(* Logix 5000 project; controller AMCI_3204_AOP_AOI_sample_RSLogix_V28 vendor 1 type 14 code 92 rev 28.11; software revision 28.00; part 2 of 3 *)

ADD_ON_INSTRUCTION AMCI_3204_AOP_Manual_Move_CW   (* revision 1.0, vendor AMCI, ExecuteEnableInFalse *)
VAR_INPUT
   axis_status_bits : INT; {required}
   channel_number : INT; {required}
   _0_normal_1_S_Curve_Acceleration : BOOL;
   _0_Triangular_1_Trapezoidal_S_Curve : BOOL;
   Programmed_speed : DINT; {required}
   Acceleration : DINT; {required}
   Deceleration : DINT; {required}
END_VAR
VAR_IN_OUT
   AMCI_3204_output_data : AM:1756_3204:O:0; {required}
END_VAR
VAR_OUTPUT
   EN : BOOL; {access Read Only, visible}
   Manual_Move_CW_occurring : BOOL; {access Read Only, visible}
   ER : BOOL; {access Read Only, visible}
END_VAR
VAR
   command_data_block : DINT[8]; {access None}
END_VAR

ROUTINE EnableInFalse   (* ladder *)
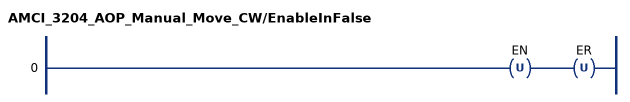
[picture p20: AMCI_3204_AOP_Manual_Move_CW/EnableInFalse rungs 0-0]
   0: OTU(EN)OTU(ER);
END_ROUTINE

ROUTINE Logic   (* ladder *)
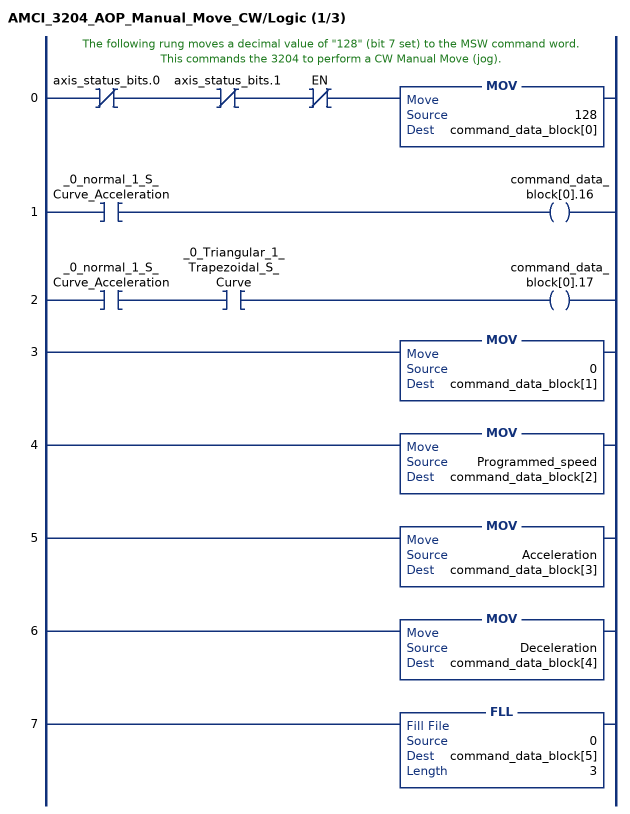
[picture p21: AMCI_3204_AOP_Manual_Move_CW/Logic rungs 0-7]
   // The following rung moves a decimal value of "128" (bit 7 set) to the MSW command word.  This commands the 3204 to perform a CW Manual Move (jog).
   0: XIO(axis_status_bits.0)XIO(axis_status_bits.1)XIO(EN)MOV(128,command_data_block[0]);
   1: XIC(_0_normal_1_S_Curve_Acceleration)OTE(command_data_block[0].16);
   2: XIC(_0_normal_1_S_Curve_Acceleration)XIC(_0_Triangular_1_Trapezoidal_S_Curve)OTE(command_data_block[0].17);
   3: MOV(0,command_data_block[1]);
   4: MOV(Programmed_speed,command_data_block[2]);
   5: MOV(Acceleration,command_data_block[3]);
   6: MOV(Deceleration,command_data_block[4]);
   7: FLL(0,command_data_block[5],3);
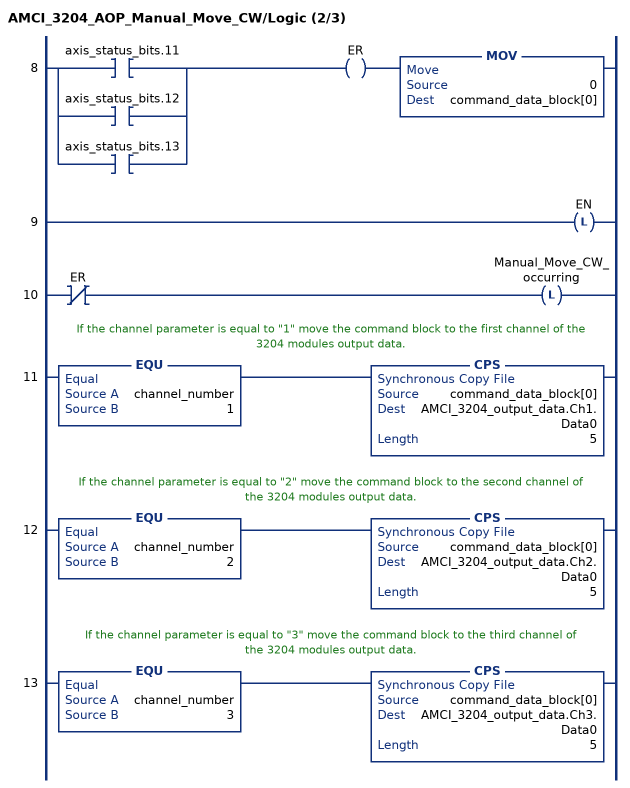
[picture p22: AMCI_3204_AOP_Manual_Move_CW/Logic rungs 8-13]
   8: [XIC(axis_status_bits.11) ,XIC(axis_status_bits.12) ,XIC(axis_status_bits.13) ]OTE(ER)MOV(0,command_data_block[0]);
   9: OTL(EN);
   10: XIO(ER)OTL(Manual_Move_CW_occurring);
   // If the channel parameter is equal to "1" move the command block to the first channel of the 3204 modules output data.
   11: EQU(channel_number,1)CPS(command_data_block[0],AMCI_3204_output_data.Ch1.Data0,5);
   // If the channel parameter is equal to "2" move the command block to the second channel of the 3204 modules output data.
   12: EQU(channel_number,2)CPS(command_data_block[0],AMCI_3204_output_data.Ch2.Data0,5);
   // If the channel parameter is equal to "3" move the command block to the third channel of the 3204 modules output data.
   13: EQU(channel_number,3)CPS(command_data_block[0],AMCI_3204_output_data.Ch3.Data0,5);
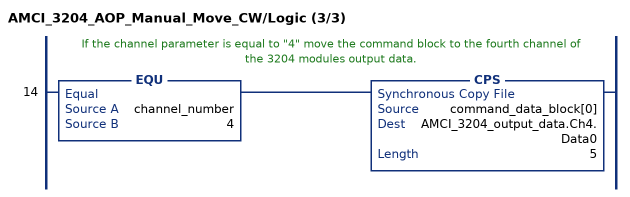
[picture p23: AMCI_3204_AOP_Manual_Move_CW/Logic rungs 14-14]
   // If the channel parameter is equal to "4" move the command block to the fourth channel of the 3204 modules output data.
   14: EQU(channel_number,4)CPS(command_data_block[0],AMCI_3204_output_data.Ch4.Data0,5);
END_ROUTINE
END_ADD_ON_INSTRUCTION

ADD_ON_INSTRUCTION AMCI_3204_AOP_Preset   (* revision 1.0, vendor AMCI, ExecuteEnableInFalse *)
VAR_INPUT
   axis_status_bits : INT; {required}
   channel_number : INT; {required}
   Target_Position : DINT; {required}
END_VAR
VAR_IN_OUT
   AMCI_3204_output_data : AM:1756_3204:O:0; {required}
END_VAR
VAR_OUTPUT
   EN : BOOL; {access Read Only, visible}
   ER : BOOL; {access Read Only, visible}
END_VAR
VAR
   command_data_block : DINT[8]; {access None}
END_VAR

ROUTINE EnableInFalse   (* ladder *)
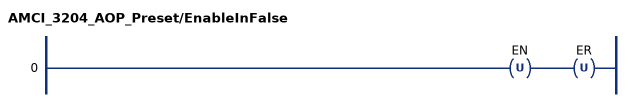
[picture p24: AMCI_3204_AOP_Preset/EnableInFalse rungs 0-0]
   0: OTU(EN)OTU(ER);
END_ROUTINE

ROUTINE Logic   (* ladder *)
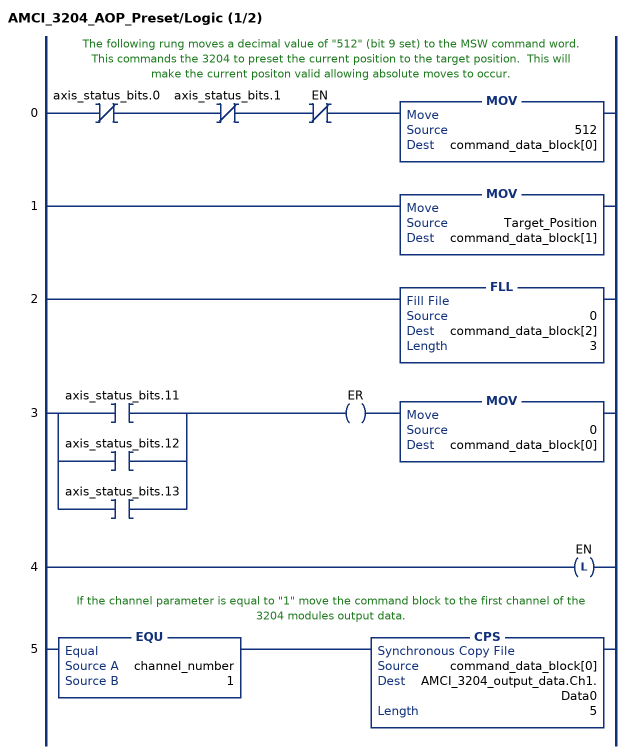
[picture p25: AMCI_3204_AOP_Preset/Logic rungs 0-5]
   // The following rung moves a decimal value of "512" (bit 9 set) to the MSW command word.  This commands the 3204 to preset the current position to the target position.  This will make the current positon valid allowing absolute moves to occur.
   0: XIO(axis_status_bits.0)XIO(axis_status_bits.1)XIO(EN)MOV(512,command_data_block[0]);
   1: MOV(Target_Position,command_data_block[1]);
   2: FLL(0,command_data_block[2],3);
   3: [XIC(axis_status_bits.11) ,XIC(axis_status_bits.12) ,XIC(axis_status_bits.13) ]OTE(ER)MOV(0,command_data_block[0]);
   4: OTL(EN);
   // If the channel parameter is equal to "1" move the command block to the first channel of the 3204 modules output data.
   5: EQU(channel_number,1)CPS(command_data_block[0],AMCI_3204_output_data.Ch1.Data0,5);
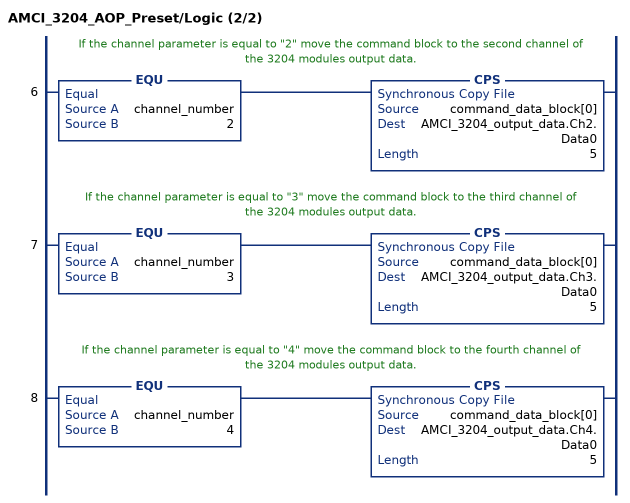
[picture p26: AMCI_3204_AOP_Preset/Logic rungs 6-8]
   // If the channel parameter is equal to "2" move the command block to the second channel of the 3204 modules output data.
   6: EQU(channel_number,2)CPS(command_data_block[0],AMCI_3204_output_data.Ch2.Data0,5);
   // If the channel parameter is equal to "3" move the command block to the third channel of the 3204 modules output data.
   7: EQU(channel_number,3)CPS(command_data_block[0],AMCI_3204_output_data.Ch3.Data0,5);
   // If the channel parameter is equal to "4" move the command block to the fourth channel of the 3204 modules output data.
   8: EQU(channel_number,4)CPS(command_data_block[0],AMCI_3204_output_data.Ch4.Data0,5);
END_ROUTINE
END_ADD_ON_INSTRUCTION

ADD_ON_INSTRUCTION AMCI_3204_AOP_Relative_Move   (* revision 1.0, vendor AMCI, ExecuteEnableInFalse *)
VAR_INPUT
   axis_status_bits : INT; {required}
   channel_number : INT; {required}
   _0_normal_1_S_Curve_Acceleration : BOOL;
   _0_Triangular_1_Trapezoidal_S_Curve : BOOL;
   Target_Position : DINT; {required}
   Programmed_speed : DINT; {required}
   Acceleration : DINT; {required}
   Deceleration : DINT; {required}
END_VAR
VAR_IN_OUT
   AMCI_3204_output_data : AM:1756_3204:O:0; {required}
END_VAR
VAR_OUTPUT
   EN : BOOL; {access Read Only, visible}
   ER : BOOL; {access Read Only, visible}
END_VAR
VAR
   command_data_block : DINT[8]; {access None}
END_VAR

ROUTINE EnableInFalse   (* ladder *)
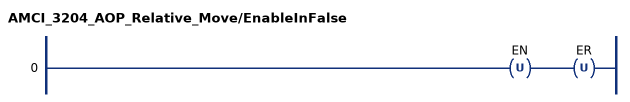
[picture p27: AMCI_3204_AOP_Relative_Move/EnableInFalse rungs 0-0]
   0: OTU(EN)OTU(ER);
END_ROUTINE

ROUTINE Logic   (* ladder *)
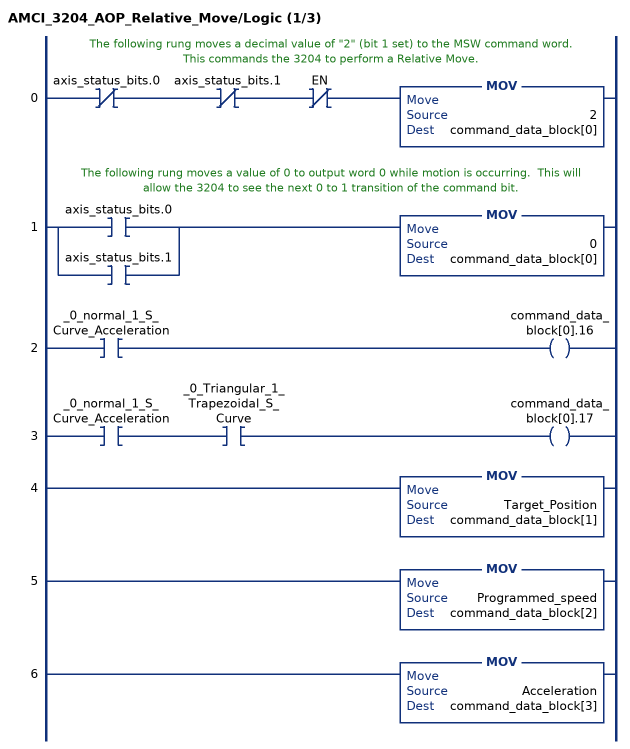
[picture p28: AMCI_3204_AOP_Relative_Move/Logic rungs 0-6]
   // The following rung moves a decimal value of "2" (bit 1 set) to the MSW command word.  This commands the 3204 to perform a Relative Move.
   0: XIO(axis_status_bits.0)XIO(axis_status_bits.1)XIO(EN)MOV(2,command_data_block[0]);
   // The following rung moves a value of 0 to output word 0 while motion is occurring.  This will allow the 3204 to see the next 0 to 1 transition of the command bit.
   1: [XIC(axis_status_bits.0) ,XIC(axis_status_bits.1) ]MOV(0,command_data_block[0]);
   2: XIC(_0_normal_1_S_Curve_Acceleration)OTE(command_data_block[0].16);
   3: XIC(_0_normal_1_S_Curve_Acceleration)XIC(_0_Triangular_1_Trapezoidal_S_Curve)OTE(command_data_block[0].17);
   4: MOV(Target_Position,command_data_block[1]);
   5: MOV(Programmed_speed,command_data_block[2]);
   6: MOV(Acceleration,command_data_block[3]);
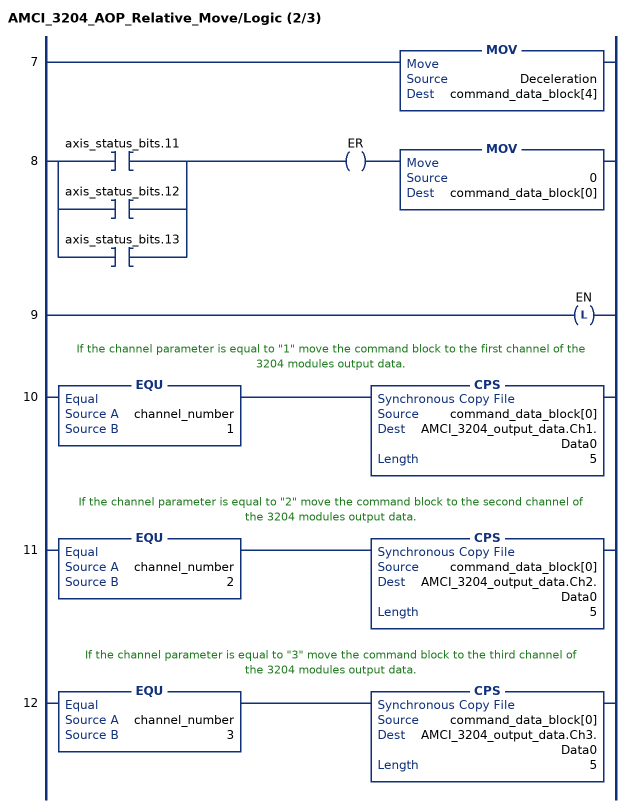
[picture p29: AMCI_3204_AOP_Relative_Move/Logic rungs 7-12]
   7: MOV(Deceleration,command_data_block[4]);
   8: [XIC(axis_status_bits.11) ,XIC(axis_status_bits.12) ,XIC(axis_status_bits.13) ]OTE(ER)MOV(0,command_data_block[0]);
   9: OTL(EN);
   // If the channel parameter is equal to "1" move the command block to the first channel of the 3204 modules output data.
   10: EQU(channel_number,1)CPS(command_data_block[0],AMCI_3204_output_data.Ch1.Data0,5);
   // If the channel parameter is equal to "2" move the command block to the second channel of the 3204 modules output data.
   11: EQU(channel_number,2)CPS(command_data_block[0],AMCI_3204_output_data.Ch2.Data0,5);
   // If the channel parameter is equal to "3" move the command block to the third channel of the 3204 modules output data.
   12: EQU(channel_number,3)CPS(command_data_block[0],AMCI_3204_output_data.Ch3.Data0,5);
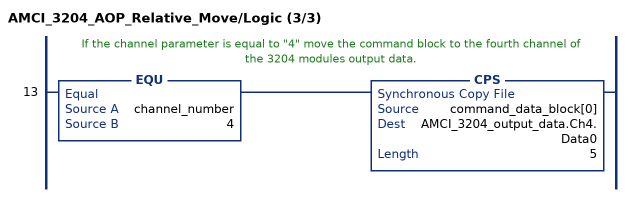
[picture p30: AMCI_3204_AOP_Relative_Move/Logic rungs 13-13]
   // If the channel parameter is equal to "4" move the command block to the fourth channel of the 3204 modules output data.
   13: EQU(channel_number,4)CPS(command_data_block[0],AMCI_3204_output_data.Ch4.Data0,5);
END_ROUTINE
END_ADD_ON_INSTRUCTION

ADD_ON_INSTRUCTION AMCI_3204_AOP_Reset_Errors   (* revision 1.0, vendor AMCI, ExecuteEnableInFalse *)
VAR_INPUT
   axis_status_bits : INT; {required}
   channel_number : INT; {required}
END_VAR
VAR_IN_OUT
   AMCI_3204_output_data : AM:1756_3204:O:0; {required}
END_VAR
VAR_OUTPUT
   EN : BOOL; {access Read Only, visible}
END_VAR
VAR
   command_data_block : DINT[8]; {access None}
END_VAR

ROUTINE EnableInFalse   (* ladder *)
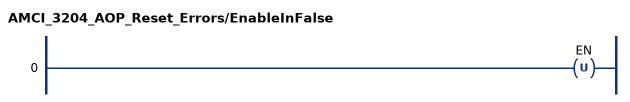
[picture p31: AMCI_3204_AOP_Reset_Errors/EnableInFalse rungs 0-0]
   0: OTU(EN);
END_ROUTINE

ROUTINE Logic   (* ladder *)
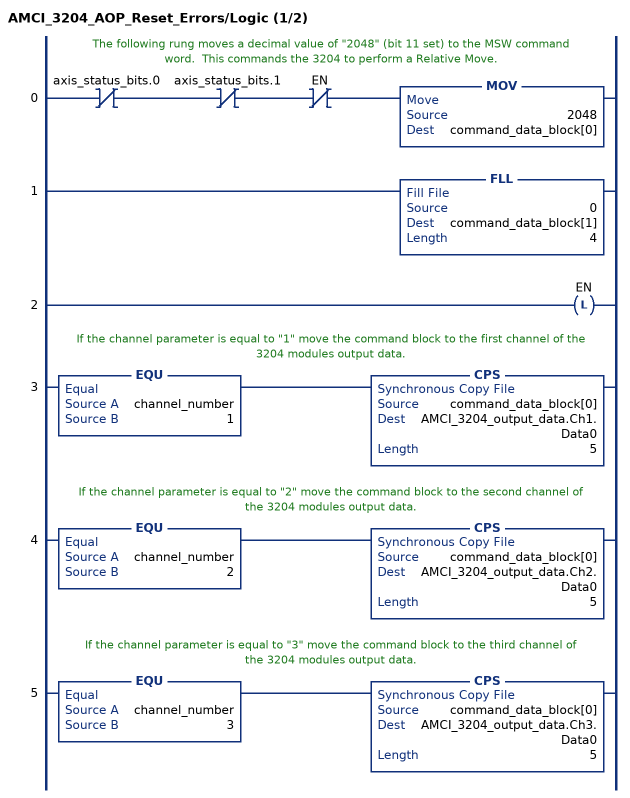
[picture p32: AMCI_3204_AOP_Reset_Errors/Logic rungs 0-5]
   // The following rung moves a decimal value of "2048" (bit 11 set) to the MSW command word.  This commands the 3204 to perform a Relative Move.
   0: XIO(axis_status_bits.0)XIO(axis_status_bits.1)XIO(EN)MOV(2048,command_data_block[0]);
   1: FLL(0,command_data_block[1],4);
   2: OTL(EN);
   // If the channel parameter is equal to "1" move the command block to the first channel of the 3204 modules output data.
   3: EQU(channel_number,1)CPS(command_data_block[0],AMCI_3204_output_data.Ch1.Data0,5);
   // If the channel parameter is equal to "2" move the command block to the second channel of the 3204 modules output data.
   4: EQU(channel_number,2)CPS(command_data_block[0],AMCI_3204_output_data.Ch2.Data0,5);
   // If the channel parameter is equal to "3" move the command block to the third channel of the 3204 modules output data.
   5: EQU(channel_number,3)CPS(command_data_block[0],AMCI_3204_output_data.Ch3.Data0,5);
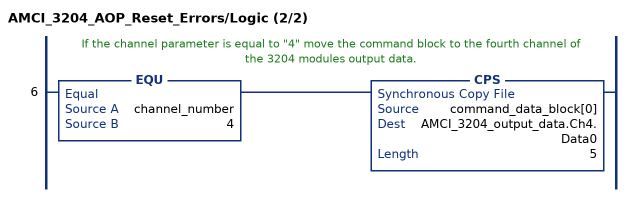
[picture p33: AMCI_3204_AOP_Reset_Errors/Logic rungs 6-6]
   // If the channel parameter is equal to "4" move the command block to the fourth channel of the 3204 modules output data.
   6: EQU(channel_number,4)CPS(command_data_block[0],AMCI_3204_output_data.Ch4.Data0,5);
END_ROUTINE
END_ADD_ON_INSTRUCTION

ADD_ON_INSTRUCTION AMCI_3204_AOP_Resume   (* revision 1.0, vendor AMCI, ExecuteEnableInFalse *)
VAR_INPUT
   channel_number : INT; {required}
END_VAR
VAR_IN_OUT
   AMCI_3204_output_data : AM:1756_3204:O:0; {required}
END_VAR
VAR
   command_data_block : DINT[8]; {access None}
END_VAR

ROUTINE EnableInFalse   (* ladder *)
END_ROUTINE

ROUTINE Logic   (* ladder *)
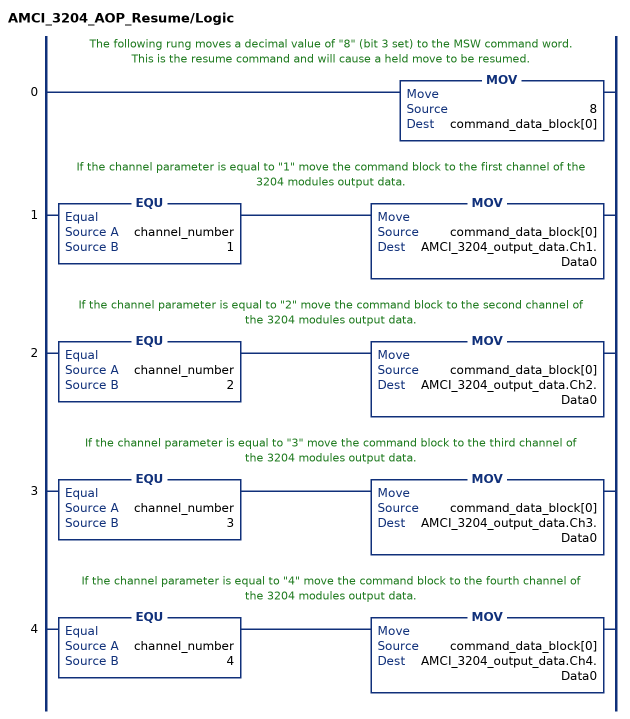
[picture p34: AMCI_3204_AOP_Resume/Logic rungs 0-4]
   // The following rung moves a decimal value of "8" (bit 3 set) to the MSW command word.  This is the resume command and will cause a held move to be resumed.
   0: MOV(8,command_data_block[0]);
   // If the channel parameter is equal to "1" move the command block to the first channel of the 3204 modules output data.
   1: EQU(channel_number,1)MOV(command_data_block[0],AMCI_3204_output_data.Ch1.Data0);
   // If the channel parameter is equal to "2" move the command block to the second channel of the 3204 modules output data.
   2: EQU(channel_number,2)MOV(command_data_block[0],AMCI_3204_output_data.Ch2.Data0);
   // If the channel parameter is equal to "3" move the command block to the third channel of the 3204 modules output data.
   3: EQU(channel_number,3)MOV(command_data_block[0],AMCI_3204_output_data.Ch3.Data0);
   // If the channel parameter is equal to "4" move the command block to the fourth channel of the 3204 modules output data.
   4: EQU(channel_number,4)MOV(command_data_block[0],AMCI_3204_output_data.Ch4.Data0);
END_ROUTINE
END_ADD_ON_INSTRUCTION

ADD_ON_INSTRUCTION AMCI_3204_AOP_Run_Blend   (* revision 1.0, vendor AMCI, ExecuteEnableInFalse *)
VAR_INPUT
   axis_status_bits : INT; {required}
   channel_number : INT; {required}
   Direction_0_for_CW_1_for_CCW : BOOL; {required}
END_VAR
VAR_IN_OUT
   AMCI_3204_output_data : AM:1756_3204:O:0; {required}
END_VAR
VAR_OUTPUT
   EN : BOOL; {access Read Only, visible}
   ER : BOOL; {access Read Only, visible}
END_VAR
VAR
   command_data_block : DINT[8]; {access None}
END_VAR

ROUTINE EnableInFalse   (* ladder *)
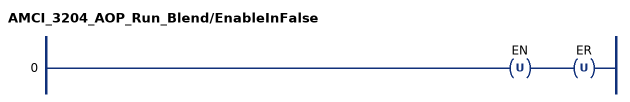
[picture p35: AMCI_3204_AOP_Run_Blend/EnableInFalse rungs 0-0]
   0: OTU(EN)OTU(ER);
END_ROUTINE

ROUTINE Logic   (* ladder *)
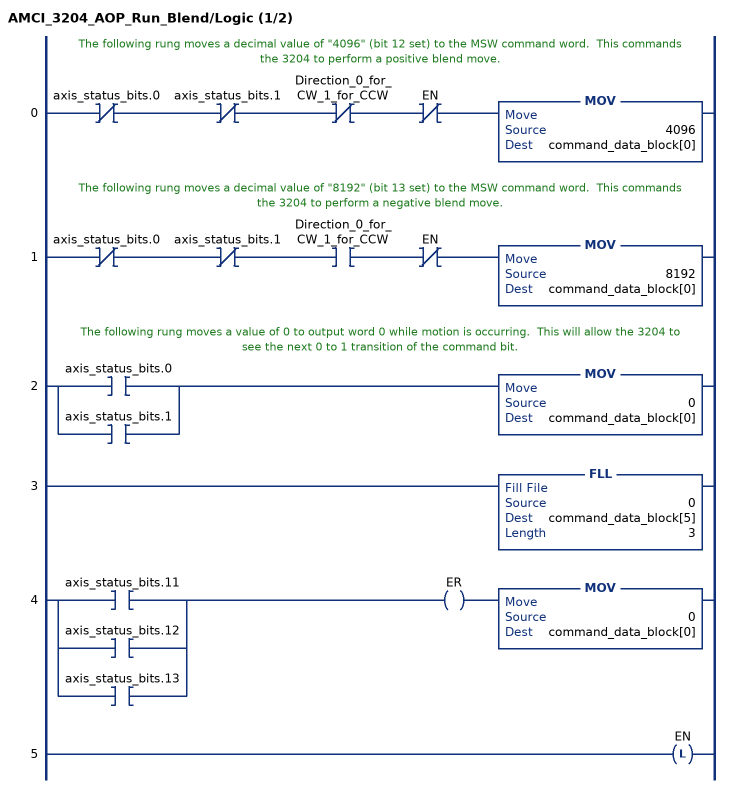
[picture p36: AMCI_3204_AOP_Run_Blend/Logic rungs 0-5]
   // The following rung moves a decimal value of "4096" (bit 12 set) to the MSW command word.  This commands the 3204 to perform a positive blend move.
   0: XIO(axis_status_bits.0)XIO(axis_status_bits.1)XIO(Direction_0_for_CW_1_for_CCW)XIO(EN)MOV(4096,command_data_block[0]);
   // The following rung moves a decimal value of "8192" (bit 13 set) to the MSW command word.  This commands the 3204 to perform a negative blend move.
   1: XIO(axis_status_bits.0)XIO(axis_status_bits.1)XIC(Direction_0_for_CW_1_for_CCW)XIO(EN)MOV(8192,command_data_block[0]);
   // The following rung moves a value of 0 to output word 0 while motion is occurring.  This will allow the 3204 to see the next 0 to 1 transition of the command bit.
   2: [XIC(axis_status_bits.0) ,XIC(axis_status_bits.1) ]MOV(0,command_data_block[0]);
   3: FLL(0,command_data_block[5],3);
   4: [XIC(axis_status_bits.11) ,XIC(axis_status_bits.12) ,XIC(axis_status_bits.13) ]OTE(ER)MOV(0,command_data_block[0]);
   5: OTL(EN);
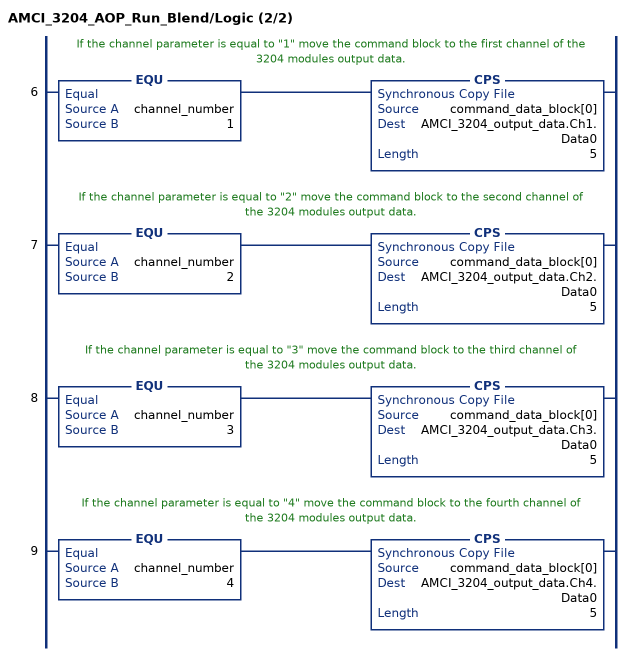
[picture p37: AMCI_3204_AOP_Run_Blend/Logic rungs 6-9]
   // If the channel parameter is equal to "1" move the command block to the first channel of the 3204 modules output data.
   6: EQU(channel_number,1)CPS(command_data_block[0],AMCI_3204_output_data.Ch1.Data0,5);
   // If the channel parameter is equal to "2" move the command block to the second channel of the 3204 modules output data.
   7: EQU(channel_number,2)CPS(command_data_block[0],AMCI_3204_output_data.Ch2.Data0,5);
   // If the channel parameter is equal to "3" move the command block to the third channel of the 3204 modules output data.
   8: EQU(channel_number,3)CPS(command_data_block[0],AMCI_3204_output_data.Ch3.Data0,5);
   // If the channel parameter is equal to "4" move the command block to the fourth channel of the 3204 modules output data.
   9: EQU(channel_number,4)CPS(command_data_block[0],AMCI_3204_output_data.Ch4.Data0,5);
END_ROUTINE
END_ADD_ON_INSTRUCTION
